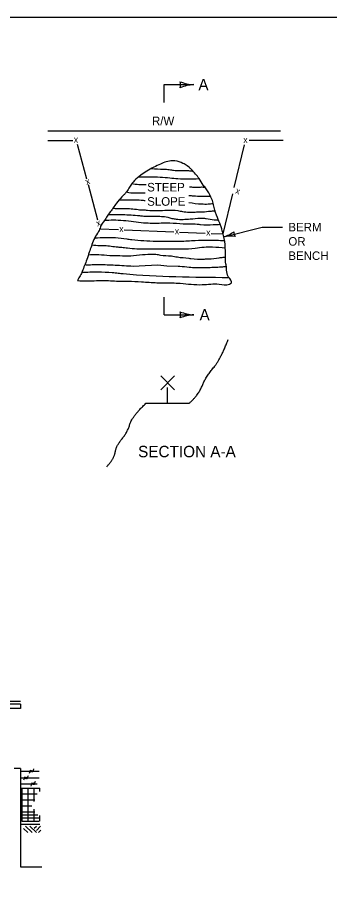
# Model space of a CAD drawing. Extents: x 49991.4 to 50021, y 49987.6 to 50011.4.
# Drawn here: x 50003.39 to 50005.57, y 49992.94 to 49999 of the extents above; entities that cross this region are included whole.
import ezdxf

# ---------------------------------------------------------------- set-up
doc = ezdxf.new("R2010")
doc.units = 0
for name, color, linetype in [('Level 1', 7, 'Continuous'), ('Level 2', 7, 'Continuous'), ('Level 3', 7, 'Continuous'), ('Level 4', 7, 'Continuous'), ('Level 6', 7, 'Continuous')]:
    doc.layers.add(name, color=color, linetype=linetype)

msp = doc.modelspace()

# ---------------------------------------------------------------- linework, layer by layer
at = {"layer": 'Level 1'}
for p, q in [((50003.5996, 49998.2035), (50005.2263, 49998.2035)), ((50003.5996, 49998.137), (50003.7745, 49998.137)), ((50003.8733, 49997.8658), (50003.8082, 49998.1089)), ((50004.9044, 49997.8082), (50004.9756, 49998.1065)), ((50005.2455, 49998.137), (50005.0077, 49998.137)), ((50003.9503, 49997.5782), (50003.884, 49997.826)), ((50004.8266, 49997.4818), (50004.8934, 49997.7618)), ((50003.9622, 49997.5174), (50004.0937, 49997.512)), ((50004.134, 49997.5104), (50004.4812, 49997.496)), ((50004.5208, 49997.4944), (50004.6997, 49997.487)), ((50004.742, 49997.4853), (50004.8266, 49997.4818)), ((50004.39, 49996.391), (50004.485, 49996.4873)), ((50004.485, 49996.391), (50004.39, 49996.4873)), ((50004.4375, 49996.2964), (50004.4375, 49996.4061)), ((50004.2862, 49996.2963), (50004.5888, 49996.2965)), ((50003.4085, 49994.1885), (50002.7485, 49994.1885)), ((50003.4085, 49994.1585), (50002.7485, 49994.1585)), ((50003.4085, 49994.208), (50002.7499, 49994.208)), ((50003.4085, 49994.1885), (50003.4085, 49994.1585)), ((50003.4085, 49993.7385), (50003.3635, 49993.7385)), ((50003.4085, 49993.7385), (50003.4085, 49993.3485)), ((50003.4085, 49993.7235), (50003.4085, 49993.7235)), ((50003.4085, 49993.7184), (50003.5389, 49993.7184)), ((50003.409, 49993.6736), (50003.4085, 49993.6736)), ((50003.409, 49993.7169), (50003.409, 49993.7169)), ((50003.409, 49993.6736), (50003.5381, 49993.6736)), ((50003.409, 49993.6302), (50003.4085, 49993.6302)), ((50003.409, 49993.6302), (50003.5249, 49993.6302)), ((50003.409, 49993.6014), (50003.5449, 49993.6014)), ((50003.4177, 49993.6014), (50003.4177, 49993.3704)), ((50003.4177, 49993.5599), (50003.5254, 49993.5599)), ((50003.4592, 49993.6014), (50003.4592, 49993.3704)), ((50003.5007, 49993.6014), (50003.5007, 49993.5071)), ((50003.5422, 49993.6014), (50003.5422, 49993.5778)), ((50003.4177, 49993.5184), (50003.5088, 49993.5184)), ((50003.4177, 49993.4769), (50003.4876, 49993.4769)), ((50003.4177, 49993.4354), (50003.5099, 49993.4354)), ((50003.5007, 49993.4542), (50003.5007, 49993.3704)), ((50003.4177, 49993.4137), (50003.5298, 49993.4137)), ((50003.4177, 49993.392), (50003.5452, 49993.392)), ((50003.4177, 49993.3704), (50003.5381, 49993.3704)), ((50003.5422, 49993.4089), (50003.5422, 49993.3704)), ((50003.409, 49993.3486), (50003.5426, 49993.3486)), ((50003.4595, 49993.2898), (50003.4304, 49993.3189)), ((50003.4895, 49993.2898), (50003.4445, 49993.3348)), ((50003.4895, 49993.2898), (50003.4445, 49993.3348)), ((50003.5195, 49993.2898), (50003.4745, 49993.3348)), ((50003.5195, 49993.2898), (50003.4745, 49993.3348)), ((50003.5045, 49993.3198), (50003.5195, 49993.3348)), ((50003.5195, 49993.3048), (50003.5495, 49993.3348)), ((50003.4595, 49993.2898), (50003.4475, 49993.3018)), ((50003.5345, 49993.2898), (50003.5503, 49993.3056))]:
    msp.add_line(p, q, dxfattribs=at)
msp.add_lwpolyline([(49999.3835, 49998.9992), (50016.7501, 49998.9992), (50016.7501, 49987.7988), (49999.3835, 49987.7988)], close=True, dxfattribs=at)
msp.add_lwpolyline([(50004.1965, 49997.2569), (50004.2801, 49997.262), (50004.3692, 49997.2663), (50004.4322, 49997.2598), (50004.5107, 49997.2559)], dxfattribs=at)
for points in [[(50003.8064, 49997.1555), (50003.8172, 49997.1753), (50003.827, 49997.1897), (50003.8406, 49997.2196), (50003.872, 49997.302), (50003.8897, 49997.3536), (50003.9044, 49997.3953), (50003.9464, 49997.4868), (50003.9552, 49997.4994), (50003.9679, 49997.5311), (50003.9952, 49997.5764), (50004.0147, 49997.6063), (50004.0361, 49997.6362), (50004.0477, 49997.6498), (50004.0555, 49997.6633), (50004.0808, 49997.6977), (50004.1168, 49997.7412), (50004.1314, 49997.7548), (50004.146, 49997.772), (50004.1664, 49997.8019), (50004.1752, 49997.8164), (50004.1956, 49997.8453), (50004.2393, 49997.8852), (50004.281, 49997.915), (50004.377, 49997.9666), (50004.4177, 49997.9838), (50004.4612, 49997.9929), (50004.4892, 49997.9947), (50004.5452, 49997.9757), (50004.5596, 49997.9684), (50004.5904, 49997.9467), (50004.6039, 49997.934), (50004.6337, 49997.9014), (50004.6577, 49997.8697), (50004.6864, 49997.8244), (50004.698, 49997.8108), (50004.7172, 49997.7836), (50004.7478, 49997.7256), (50004.7544, 49997.7066), (50004.7629, 49997.6668), (50004.7858, 49997.597), (50004.8077, 49997.5445), (50004.8239, 49997.4911), (50004.8343, 49997.4494), (50004.8416, 49997.3643), (50004.8423, 49997.3181), (50004.845, 49997.2728), (50004.8478, 49997.2583), (50004.8505, 49997.2293), (50004.8638, 49997.1804), (50004.8839, 49997.1388), (50004.8713, 49997.1306), (50004.7978, 49997.1306), (50004.6799, 49997.127), (50004.5263, 49997.1361), (50004.4703, 49997.1389), (50004.363, 49997.1407), (50004.2558, 49997.1471), (50004.1621, 49997.1507), (50004.106, 49997.1507), (50003.9978, 49997.1562), (50003.9727, 49997.1562), (50003.8422, 49997.1535), (50003.8064, 49997.1555)], [(50004.3238, 49997.9395), (50004.4106, 49997.9358), (50004.4493, 49997.9331), (50004.4792, 49997.9286), (50004.5227, 49997.9259), (50004.5836, 49997.9258)], [(50004.5836, 49997.9258), (50004.598, 49997.9242), (50004.6142, 49997.9233)], [(50004.234, 49997.881), (50004.3862, 49997.8806), (50004.4528, 49997.8752), (50004.5089, 49997.8697), (50004.5804, 49997.8679), (50004.6578, 49997.8696)], [(50004.1876, 49997.8349), (50004.2361, 49997.829), (50004.2875, 49997.829)], [(50004.5911, 49997.8126), (50004.6187, 49997.8099), (50004.6448, 49997.809), (50004.6757, 49997.8108), (50004.6989, 49997.8097)], [(50004.1488, 49997.7758), (50004.1653, 49997.7729), (50004.2816, 49997.7705)], [(50004.587, 49997.7523), (50004.6174, 49997.7492), (50004.7376, 49997.7477)], [(50004.0986, 49997.72), (50004.2114, 49997.7213), (50004.2655, 49997.7176), (50004.2808, 49997.7157)], [(50004.5858, 49997.702), (50004.6761, 49997.6922), (50004.7205, 49997.6921), (50004.7568, 49997.6962)], [(50004.023, 49997.6183), (50004.1094, 49997.618), (50004.2263, 49997.6117), (50004.2543, 49997.6089), (50004.2881, 49997.6062), (50004.3471, 49997.6071), (50004.3944, 49997.6053), (50004.4389, 49997.5989), (50004.4678, 49997.5908), (50004.4832, 49997.5881), (50004.4968, 49997.5862), (50004.5963, 49997.5871), (50004.6669, 49997.5925), (50004.6949, 49997.5916), (50004.7084, 49997.5907), (50004.7625, 49997.5816), (50004.7857, 49997.5807), (50004.7939, 49997.5776)], [(50004.0556, 49997.6634), (50004.0864, 49997.6597), (50004.1338, 49997.6597), (50004.2314, 49997.6533), (50004.2497, 49997.6506), (50004.2806, 49997.6497), (50004.297, 49997.6479), (50004.4362, 49997.6487), (50004.5087, 49997.646), (50004.5425, 49997.6388), (50004.5656, 49997.636), (50004.6101, 49997.6342), (50004.6507, 49997.6369), (50004.6806, 49997.6369), (50004.7367, 49997.6423), (50004.7512, 49997.6432), (50004.7657, 49997.6441), (50004.7702, 49997.6424)], [(50003.9966, 49997.5786), (50004.057, 49997.58), (50004.2, 49997.5691), (50004.2695, 49997.5609), (50004.3005, 49997.5591), (50004.4241, 49997.5591), (50004.4541, 49997.5591), (50004.5459, 49997.5536), (50004.6068, 49997.5536), (50004.656, 49997.55), (50004.6686, 49997.5482), (50004.7575, 49997.5472), (50004.8059, 49997.5496)], [(50003.9298, 49997.4542), (50004.0721, 49997.4568), (50004.1513, 49997.4477), (50004.187, 49997.4431), (50004.357, 49997.4322), (50004.388, 49997.4322), (50004.4566, 49997.4304), (50004.5252, 49997.4313), (50004.6315, 49997.4367), (50004.7214, 49997.4394), (50004.8366, 49997.4352)], [(50003.9085, 49997.4061), (50003.9636, 49997.4016), (50003.9964, 49997.4016), (50004.0892, 49997.3907), (50004.1172, 49997.3889), (50004.1568, 49997.3844), (50004.2872, 49997.3771), (50004.3848, 49997.378), (50004.5384, 49997.377), (50004.6303, 49997.3824), (50004.6931, 49997.3897), (50004.7521, 49997.3906), (50004.8409, 49997.3852)], [(50003.8836, 49997.3357), (50003.9383, 49997.3391), (50004.0117, 49997.3328), (50004.1035, 49997.33), (50004.1798, 49997.3291), (50004.261, 49997.3373), (50004.3383, 49997.34), (50004.3557, 49997.3399), (50004.3876, 49997.3345), (50004.4639, 49997.3281), (50004.5064, 49997.3209), (50004.5856, 49997.3118), (50004.5991, 49997.31), (50004.6967, 49997.3064), (50004.7238, 49997.3072), (50004.7982, 49997.3154), (50004.8117, 49997.3172), (50004.8423, 49997.32)], [(50003.8594, 49997.2675), (50003.8749, 49997.2658), (50003.9203, 49997.2685), (50003.9609, 49997.2685), (50004.0701, 49997.2639), (50004.1965, 49997.2569)], [(50004.5107, 49997.2559), (50004.5223, 49997.2557), (50004.588, 49997.2502), (50004.6344, 49997.2466), (50004.7078, 49997.2466), (50004.8151, 49997.252), (50004.8484, 49997.2542)], [(50003.8386, 49997.2145), (50003.9508, 49997.216), (50004.0503, 49997.2123), (50004.0918, 49997.2078), (50004.1276, 49997.2042), (50004.8649, 49997.1776)], [(50003.5003, 49993.7352), (50003.4898, 49993.7142), (50003.4898, 49993.7247), (50003.4793, 49993.7142), (50003.4793, 49993.7247), (50003.4688, 49993.7037)], [(50003.4615, 49993.6874), (50003.451, 49993.6664), (50003.451, 49993.6769), (50003.4405, 49993.6664), (50003.4405, 49993.6769), (50003.43, 49993.6559)], [(50003.5114, 49993.6464), (50003.5009, 49993.6254), (50003.5009, 49993.6359), (50003.4904, 49993.6254), (50003.4904, 49993.6359), (50003.4799, 49993.6149)]]:
    msp.add_spline(points, degree=3, dxfattribs=at)
for points in [[(50004.5888, 49996.2965), (50004.654, 49996.3537), (50004.7052, 49996.4831), (50004.8057, 49996.5987), (50004.8621, 49996.7435)], [(50004.0118, 49995.8513), (50004.0647, 49995.9103), (50004.0786, 49995.9992), (50004.156, 49996.091), (50004.1906, 49996.2049), (50004.2862, 49996.2963)]]:
    msp.add_open_spline(points, degree=2, dxfattribs=at)
at = {"layer": 'Level 3'}
for p, q in [((50004.8317, 49997.4619), (50005.1001, 49997.5296)), ((50005.1001, 49997.5296), (50005.2425, 49997.5296))]:
    msp.add_line(p, q, dxfattribs=at)
for centre, radius, start, end in [((50004.6313, 49998.8095), 0.2822, 247.72521, 267.90872), ((50004.4583, 49998.5268), 0.0695, 342.40802, 18.13038), ((50004.637, 49998.2322), 0.2957, 93.09651, 112.34636), ((50004.7614, 49997.6841), 0.233, 287.56141, 306.81126), ((50004.9557, 49997.4945), 0.0548, 176.87292, 212.59528), ((50004.8794, 49997.2448), 0.2223, 82.19011, 102.37362), ((50004.6313, 49997.1979), 0.2822, 247.72521, 267.90872), ((50004.4583, 49996.9151), 0.0695, 342.40802, 18.13038), ((50004.637, 49996.6206), 0.2957, 93.09651, 112.34636)]:
    msp.add_arc(centre, radius, start, end, dxfattribs=at)
at = {"layer": 'Level 4'}
for p, q in [((50003.4085, 49993.3485), (50003.4085, 49993.0485)), ((50003.4085, 49993.0485), (50003.5585, 49993.0485))]:
    msp.add_line(p, q, dxfattribs=at)
at = {"layer": 'Level 6'}
for p, q in [((50004.4129, 49998.4035), (50004.4129, 49998.5275)), ((50004.4129, 49998.5275), (50004.621, 49998.5275)), ((50004.4129, 49996.9159), (50004.4129, 49997.0399)), ((50004.4129, 49996.9159), (50004.621, 49996.9159))]:
    msp.add_line(p, q, dxfattribs=at)

# ---------------------------------------------------------------- texts
at = {"layer": 'Level 1'}
for p in [(50003.7814, 49998.1207), (50004.9673, 49998.1188), (50004.0995, 49997.4951), (50004.4879, 49997.4792), (50004.7074, 49997.4701)]:
    msp.add_text('x', height=0.0451, dxfattribs=at).set_placement(p)
for rotation, p in [(19.86391, (50003.871, 49997.8247)), (340.09938, (50004.9078, 49997.7672)), (19.86391, (50003.9467, 49997.5329))]:
    msp.add_text('x', height=0.045, rotation=rotation, dxfattribs=at).set_placement(p)
at = {"layer": 'Level 2'}
for s, height, p in [('A', 0.08, (50004.6528, 49998.4875)), ('R/W', 0.06, (50004.3284, 49998.2435)), ('STEEP', 0.06, (50004.2948, 49997.7795)), ('SLOPE', 0.06, (50004.2948, 49997.6795)), ('BERM', 0.06, (50005.2825, 49997.4996)), ('OR ', 0.06, (50005.2825, 49997.3996)), ('BENCH', 0.06, (50005.2825, 49997.2996)), ('A', 0.08, (50004.661, 49996.8759)), ('SECTION A-A', 0.08, (50004.2311, 49995.918))]:
    msp.add_text(s, height=height, dxfattribs=at).set_placement(p)

doc.saveas('drawing.dxf')
